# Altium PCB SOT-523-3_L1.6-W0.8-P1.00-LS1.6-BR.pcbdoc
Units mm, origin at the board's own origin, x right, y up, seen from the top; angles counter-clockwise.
Board outline 14.57 x 14.68 mm, 2 copper layers (Top Layer, Bottom Layer), stack 0 mm thick; 1 components, 0 nets, 3 pads, 0 vias.
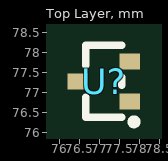
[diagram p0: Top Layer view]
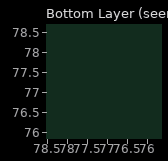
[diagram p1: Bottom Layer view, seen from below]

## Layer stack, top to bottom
Top Layer: signal copper (thickness not stored)
Bottom Layer: signal copper (thickness not stored)

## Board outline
84.419,69.85 69.85,69.85 69.85,84.527 84.419,84.527

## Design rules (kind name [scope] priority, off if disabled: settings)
PasteMaskExpansion "Paste Mask Expansion" [All] p1: expansion=0
SolderMaskExpansion "Solder Mask Expansion" [IsVia] p1: expansion=-25.4 istentingtop=TRUE
SolderMaskExpansion "Solder Mask Expansion" [All] p2: expansion=0.051 istentingtop=FALSE

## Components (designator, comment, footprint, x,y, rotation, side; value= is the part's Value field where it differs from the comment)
U? "" SOT-523-3_L1.6-W0.8-P1.00-LS1.6-BR 77.105,77.277 r0 top

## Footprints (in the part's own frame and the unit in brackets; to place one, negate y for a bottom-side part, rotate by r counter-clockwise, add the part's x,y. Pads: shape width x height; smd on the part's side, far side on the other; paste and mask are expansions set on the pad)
SOT-523-3_L1.6-W0.8-P1.00-LS1.6-BR [mm]
  rect 0.51x0.4 smd: 1(0.65,-0.5) 2(0.65,0.5) 3(-0.65,0)
  silkscreen extent -0.45,-1.08 0.83,0.9

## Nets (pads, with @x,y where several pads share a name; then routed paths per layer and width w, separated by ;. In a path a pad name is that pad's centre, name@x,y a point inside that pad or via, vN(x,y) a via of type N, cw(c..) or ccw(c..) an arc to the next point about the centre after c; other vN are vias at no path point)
pads on no net: U?.1 U?.2 U?.3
